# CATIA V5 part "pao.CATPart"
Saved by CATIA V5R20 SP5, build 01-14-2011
Part number: Part1
Bounding box of the stored display mesh (mm): x -51.82 to 2850, y -350 to 350, z -290.512 to 314.81
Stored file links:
  C:\Documents and Settings\Student\桌面\zuoping\pao.CATPart
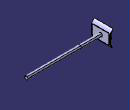
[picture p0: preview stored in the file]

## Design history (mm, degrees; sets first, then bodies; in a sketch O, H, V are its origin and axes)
Body1 (main body)
  Sketch1 on yz-plane, origin (0, 0, 0), H (0, 1, 0), V (0, 0, 1)
    line L1 (275, 50) -> (275, -50)
    line L2 (275, -50) -> (-275, -50)
    line L3 (-275, -50) -> (-275, 50)
    line L4 (-275, 50) -> (275, 50)
    distance L1 L3 = 550
    distance L2 L4 = 100
    vertical: L1 V, L3 V
    horizontal: L2 H, L4 H
    equidistance: L1 L3 O, L2 L4 O
  Pad1: profile Sketch1, direction (1, 0, 0), length 50
  Sketch2 on face of Pad1 from Sketch1.L1, origin (0, 275, 0), H (-1, 0, 0), V (0, 0, 1)
    circle A1 centre (0, 0) radius 40
    radius A1 = 40
  Pad2: profile Sketch2, direction (0, 1, 0), length 30
  Mirror1: of Pad2, about zx-plane
  Fillet1: radius 20, on end face of Pad1; edge [face of Pad1 from Sketch1.L4 | end face of Pad1]
  Plane1: type Offset, RefPlane yz-plane, Offset 50
  Plane2: type Offset, RefPlane Plane1, Offset 50
  Plane3: type Offset, RefPlane end face of Pad1, Offset 2800, reversed
  Sketch3 on end face of Pad1, origin (50, 0, 0), H (0, 1, 0), V (0, 0, 1)
    circle A1 centre (0, 0) radius 65
    radius A1 = 65
  Sketch4 on Plane3, origin (2850, 0, 0), H (0, -1, 0), V (0, 0, 1)
    circle A1 centre (0, 0) radius 62.5
    radius A1 = 62.5
  Loft1: solid, Sections (Sketch3; Sketch4)
  Sketch5 on face of Loft1, origin (2850, 0, 0), H (0, 1, 0), V (0, 0, 1)
    circle A1 centre (0, 0) radius 61
    radius A1 = 61
  Pocket1: profile Sketch5, direction (-1, 0, 0), length 2000
  Sketch6 on end face of Pad1, origin (50, 0, 0), H (0, 1, 0), V (0, 0, 1)
    line L1 (310, 200) -> (310, -200)
    line L2 (310, -200) -> (-310, -200)
    line L3 (-310, -200) -> (-310, 200)
    line L4 (-310, 200) -> (310, 200)
    length L4 = 620
    length L1 = 400
    vertical: L1 V, L3 V
    horizontal: L2 H, L4 H
    equidistance: L1 L3 O, L2 L4 O
  Pad3: profile Sketch6, direction (1, 0, 0), length 10
  Fillet2: radius 5, on edge [face of Pad3 from Sketch6.L4 | end face of Pad3]; edge [face of Pad3 from Sketch6.L1 | end face of Pad3]; edge [face of Pad3 from Sketch6.L2 | end face of Pad3]; edge [face of Pad3 from Sketch6.L3 | end face of Pad3]
  Sketch7 on zx-plane, origin (0, 0, 0), H (-1, 0, 0), V (0, 0, 1)
    point P1 (-57.4292, 0)
    line L1 (-57.4292, 0) -> (-57.4292, 166.0972)
    point P2 (-57.4292, 166.0972)
    line L2 (-57.4292, 0) -> (-57.4292, -145.9892)
    point P3 (-57.4292, -145.9892)
    spline S1 through (-57.4292, 166.0972) (9.8011, 272.9187) (51.8201, 314.8095)
    spline S2 through (-57.4292, -145.9892) (-30.1169, -231.8654) (20.3058, -290.5125)
    line L3 (-37.6384, -145.9892) -> (-30.1169, 166.0972)
    line L4 (-30.1169, 166.0972) -> (51.8201, 314.8095)
    point P6 (51.8201, 314.8095)
    line L5 (-37.6384, -145.9892) -> (20.3058, -290.5125)
    point P7 (20.3058, -290.5125)
    point P8 (-57.4292, 166.0972)
    point P9 (-57.4292, -145.9892)
    point P10 (20.3058, -290.5125)
    point P11 (51.8201, 314.8095)
    coincidence: P1 H, P8 P2, P9 P3, L4 P11, P6 S1, L5 P10, P7 S2, P11 P6, P10 P7
    vertical: L1 V, L2 V
  Pad4: profile Sketch7, direction (0, 1, 0), length 350, mirrored extent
